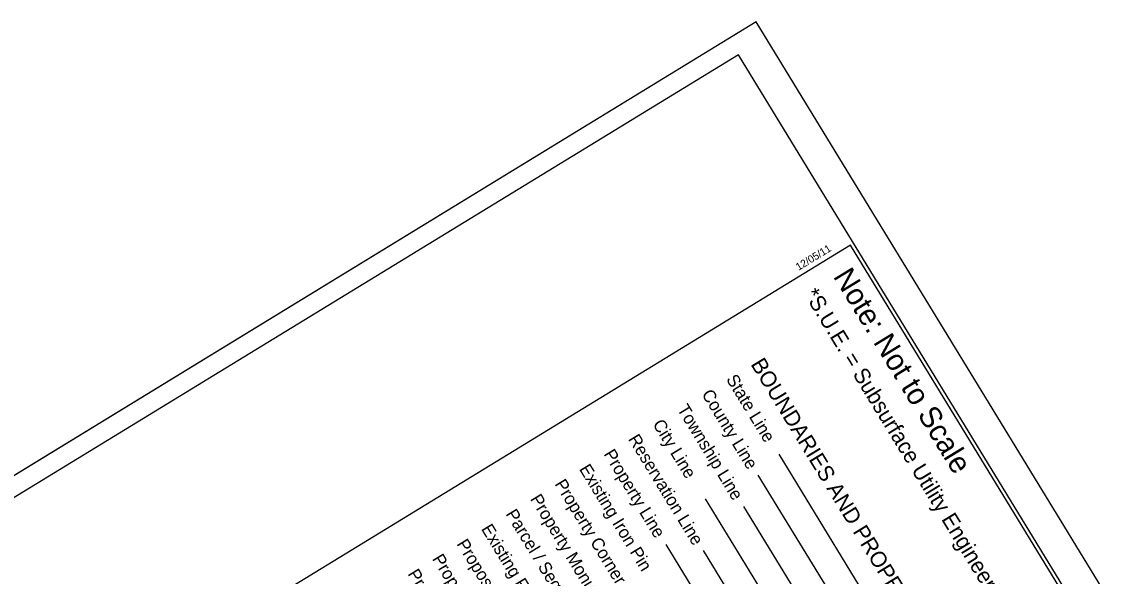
# Model space of a CAD drawing. Extents: x 1750583 to 1791140, y 783580 to 827376.
# Drawn here: x 1782342 to 1783107, y 785205 to 785591 of the extents above; entities that cross this region are included whole.
import ezdxf

# ---------------------------------------------------------------- set-up
doc = ezdxf.new("R2010")
doc.units = 0
for name, color, linetype in [('Sheet Cutting Line CELL', 7, 'Continuous'), ('Sheet Plot Border Inside CELL', 7, 'Continuous'), ('Sheet Plot Border Outside CELL', 7, 'Continuous'), ('Sheet Summary Guardrail CELL', 7, 'Continuous'), ('Sheet Symbology CELL', 7, 'Continuous')]:
    doc.layers.add(name, color=color, linetype=linetype)

msp = doc.modelspace()

# ---------------------------------------------------------------- linework, layer by layer
at = {"layer": 'Sheet Cutting Line CELL'}
for p, q in [((1782853.72, 785590.64), (1781915.06, 785017.12)), ((1783731.73, 784153.64), (1782853.72, 785590.64))]:
    msp.add_line(p, q, dxfattribs=at)
at = {"layer": 'Sheet Plot Border Inside CELL'}
msp.add_lwpolyline([(1781941, 785017.73), (1782809.88, 783595.67), (1783710.22, 784145.77), (1782841.34, 785567.84)], close=True, dxfattribs=at)
at = {"layer": 'Sheet Plot Border Outside CELL'}
msp.add_lwpolyline([(1781915.06, 785017.12), (1782793.07, 783580.12), (1783731.73, 784153.64), (1782853.72, 785590.64)], close=True, dxfattribs=at)
at = {"layer": 'Sheet Symbology CELL'}
for p, q in [((1782968.74, 785127.57), (1782869.68, 785289.69)), ((1782951.67, 785117.14), (1782855.21, 785275.01)), ((1782917.54, 785096.29), (1782818.48, 785258.41)), ((1782934.6, 785106.72), (1782845.08, 785253.23)), ((1782883.4, 785075.43), (1782791, 785226.67)), ((1782900.47, 785085.86), (1782817.01, 785222.46))]:
    msp.add_line(p, q, dxfattribs=at)
msp.add_lwpolyline([(1783701.53, 784155.11), (1782919.46, 785435.1), (1782024.34, 784888.18), (1782806.41, 783608.19)], close=True, dxfattribs=at)

# ---------------------------------------------------------------- texts
at = {"layer": 'Sheet Summary Guardrail CELL'}
msp.add_text('12/05/11', height=5.25, rotation=31.42495, dxfattribs=at).set_placement((1782883.24, 785417.24))
at = {"layer": 'Sheet Symbology CELL'}
for s, height, p in [('Note: Not to Scale', 15, (1782907.03, 785413.38)), ('*S.U.E. = Subsurface Utility Engineering', 11, (1782886.72, 785400.96)), ('BOUNDARIES AND PROPERTY:', 11, (1782849.55, 785352.28)), ('State Line', 8.75, (1782832.5, 785341.84)), ('County Line', 8.75, (1782815.43, 785331.42)), ('Township Line', 8.75, (1782798.37, 785320.99)), ('City Line', 8.75, (1782781.3, 785310.56)), ('Reservation Line', 8.75, (1782764.23, 785300.13)), ('Property Line', 8.75, (1782747.17, 785289.71)), ('Existing Iron Pin', 8.75, (1782730.1, 785279.28)), ('Property Corner', 8.75, (1782713.03, 785268.85)), ('Property Monument', 8.75, (1782695.97, 785258.42)), ('Parcel / Sequence Number', 8.75, (1782678.9, 785247.99)), ('Existing Fence Line', 8.75, (1782661.83, 785237.57)), ('Proposed Woven Wire Fence', 8.75, (1782644.77, 785227.14)), ('Proposed Chain Link Fence', 8.75, (1782627.7, 785216.71)), ('Proposed Barbed Wire Fence', 8.75, (1782610.63, 785206.28))]:
    msp.add_text(s, height=height, rotation=301.42495, dxfattribs=at).set_placement(p)

doc.saveas('drawing.dxf')
